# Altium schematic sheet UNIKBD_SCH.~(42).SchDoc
size A4
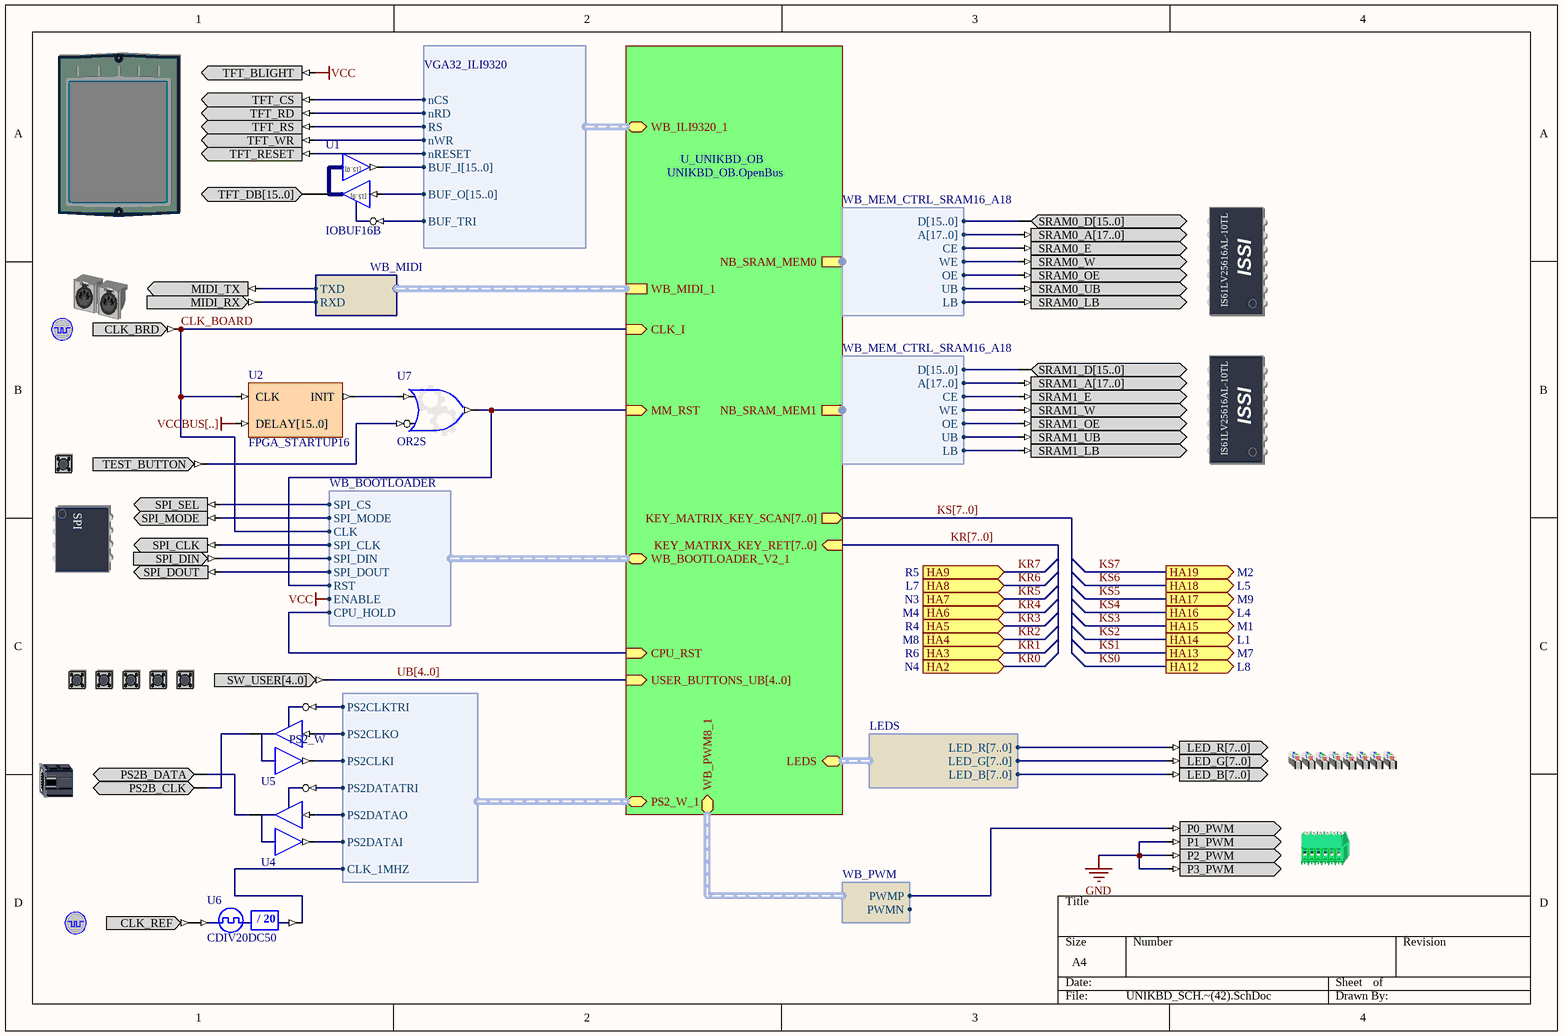
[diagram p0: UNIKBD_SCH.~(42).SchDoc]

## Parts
(Parts that share a designator on the sheet are numbered #1, #2 ... from top to bottom, then left to right.)
?#1  TFT_LCD  (value not drawn)
?#2  SRAM0  (value not drawn)
?#3  MIDI  (value not drawn)
?#4  CLOCK_BOARD  (value not drawn)
?#5  SRAM1  (value not drawn)
?#6  TEST_BUTTON  (value not drawn)
?#7  SERIALFMEMORY  (value not drawn)
?#8  USER_BUTTONS  (value not drawn)
?#9  LEDS_RGB  (value not drawn)
?#10  PS2B  (value not drawn)
?#11  PWM  (value not drawn)
?#12  CLOCK_REFERENCE  (value not drawn)
U1  IOBUF16B
U2  FPGA_STARTUP16
U4  IOBUF  (value not drawn)
U5  IOBUF  (value not drawn)
U6  CDIV20DC50
U7  OR2S

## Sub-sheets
U_UNIKBD_OB = UNIKBD_OB.OpenBus: KEY_MATRIX_KEY_SCAN[7..0] (out), KEY_MATRIX_KEY_RET[7..0] (in), WB_MIDI_1 (harness WB_MIDI), NB_SRAM_MEM0 (harness WB_MEM_CTRL_SRAM16_A18), NB_SRAM_MEM1 (harness WB_MEM_CTRL_SRAM16_A18), CLK_I (in), USER_BUTTONS_UB[4..0] (in), PS2_W_1 (harness PS2_W), LEDS (harness LEDS), WB_PWM8_1 (harness WB_PWM), WB_BOOTLOADER_V2_1 (harness WB_BOOTLOADER), MM_RST (in), CPU_RST (in), WB_ILI9320_1 (harness VGA32_ILI9320)

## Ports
HA2 (in, see N4), HA3 (in, see R6), HA4 (in, see M8), HA5 (in, see R4), HA6 (in, see M4), HA7 (in, see N3), HA8 (in, see L7), HA9 (in, see R5), HA12 (out, see L8), HA13 (out, see M7), HA14 (out, see L1), HA15 (out, see M1), HA16 (out, see L4), HA17 (out, see M9), HA18 (out, see L5), HA19 (out, see M2)

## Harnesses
WB_MEM_CTRL_SRAM16_A18: D[15..0], A[17..0], CE, WE, OE, UB, LB
WB_MIDI: RXD, TXD
LEDS: LED_R[7..0], LED_G[7..0], LED_B[7..0]
PS2_W: PS2CLKTRI, PS2CLKO, PS2CLKI, PS2DATATRI, PS2DATAO, PS2DATAI, CLK_1MHZ
WB_PWM: PWMN, PWMP
WB_BOOTLOADER: SPI_DOUT, SPI_DIN, SPI_CLK, SPI_MODE, SPI_CS, CLK, RST, ENABLE, CPU_HOLD
VGA32_ILI9320: BUF_TRI, BUF_O[15..0], BUF_I[15..0], nRESET, nWR, RS, nRD, nCS

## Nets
GND: ?#11.P1_PWM ?#11.P2_PWM ?#11.P3_PWM
VCC: ?#1.TFT_BLIGHT ; sheet U_UNIKBD_OB/WB_BOOTLOADER_V2_1.ENABLE
VCCBUS[..]: U2.DELAY[15..0]
CLK_BOARD: ?#4.CLK_BRD U2.CLK ; sheet U_UNIKBD_OB/CLK_I, sheet U_UNIKBD_OB/WB_BOOTLOADER_V2_1.CLK
Net?#1_TFT_CS: ?#1.TFT_CS ; sheet U_UNIKBD_OB/WB_ILI9320_1.nCS
Net?#1_TFT_DB[15..0]: ?#1.TFT_DB[15..0] U1.IO[15..0]
Net?#1_TFT_RD: ?#1.TFT_RD ; sheet U_UNIKBD_OB/WB_ILI9320_1.nRD
Net?#1_TFT_RESET: ?#1.TFT_RESET ; sheet U_UNIKBD_OB/WB_ILI9320_1.nRESET
Net?#1_TFT_RS: ?#1.TFT_RS ; sheet U_UNIKBD_OB/WB_ILI9320_1.RS
Net?#1_TFT_WR: ?#1.TFT_WR ; sheet U_UNIKBD_OB/WB_ILI9320_1.nWR
Net?#2_SRAM0_E: ?#2.SRAM0_E ; sheet U_UNIKBD_OB/NB_SRAM_MEM0.CE
Net?#2_SRAM0_LB: ?#2.SRAM0_LB ; sheet U_UNIKBD_OB/NB_SRAM_MEM0.LB
Net?#2_SRAM0_OE: ?#2.SRAM0_OE ; sheet U_UNIKBD_OB/NB_SRAM_MEM0.OE
Net?#2_SRAM0_UB: ?#2.SRAM0_UB ; sheet U_UNIKBD_OB/NB_SRAM_MEM0.UB
Net?#2_SRAM0_W: ?#2.SRAM0_W ; sheet U_UNIKBD_OB/NB_SRAM_MEM0.WE
Net?#3_MIDI_RX: ?#3.MIDI_RX ; sheet U_UNIKBD_OB/WB_MIDI_1.RXD
Net?#3_MIDI_TX: ?#3.MIDI_TX ; sheet U_UNIKBD_OB/WB_MIDI_1.TXD
Net?#5_SRAM1_E: ?#5.SRAM1_E ; sheet U_UNIKBD_OB/NB_SRAM_MEM1.CE
Net?#5_SRAM1_LB: ?#5.SRAM1_LB ; sheet U_UNIKBD_OB/NB_SRAM_MEM1.LB
Net?#5_SRAM1_OE: ?#5.SRAM1_OE ; sheet U_UNIKBD_OB/NB_SRAM_MEM1.OE
Net?#5_SRAM1_UB: ?#5.SRAM1_UB ; sheet U_UNIKBD_OB/NB_SRAM_MEM1.UB
Net?#5_SRAM1_W: ?#5.SRAM1_W ; sheet U_UNIKBD_OB/NB_SRAM_MEM1.WE
Net?#6_TEST_BUTTON: ?#6.TEST_BUTTON U7.I1
Net?#7_SPI_CLK: ?#7.SPI_CLK ; sheet U_UNIKBD_OB/WB_BOOTLOADER_V2_1.SPI_CLK
Net?#7_SPI_DIN: ?#7.SPI_DIN ; sheet U_UNIKBD_OB/WB_BOOTLOADER_V2_1.SPI_DIN
Net?#7_SPI_DOUT: ?#7.SPI_DOUT ; sheet U_UNIKBD_OB/WB_BOOTLOADER_V2_1.SPI_DOUT
Net?#7_SPI_MODE: ?#7.SPI_MODE ; sheet U_UNIKBD_OB/WB_BOOTLOADER_V2_1.SPI_MODE
Net?#7_SPI_SEL: ?#7.SPI_SEL ; sheet U_UNIKBD_OB/WB_BOOTLOADER_V2_1.SPI_CS
Net?#10_PS2B_CLK: ?#10.PS2B_CLK U5.IO
Net?#10_PS2B_DATA: ?#10.PS2B_DATA U4.IO
Net?#11_P0_PWM: ?#11.P0_PWM ; sheet U_UNIKBD_OB/WB_PWM8_1.PWMP
Net?#12_CLK_REF: ?#12.CLK_REF U6.CLKIN
NetU1_T: U1.T ; sheet U_UNIKBD_OB/WB_ILI9320_1.BUF_TRI
NetU2_INIT: U2.INIT U7.I0
NetU4_I: U4.I ; sheet U_UNIKBD_OB/PS2_W_1.PS2DATAO
NetU4_O: U4.O ; sheet U_UNIKBD_OB/PS2_W_1.PS2DATAI
NetU4_T: U4.T ; sheet U_UNIKBD_OB/PS2_W_1.PS2DATATRI
NetU5_I: U5.I ; sheet U_UNIKBD_OB/PS2_W_1.PS2CLKO
NetU5_O: U5.O ; sheet U_UNIKBD_OB/PS2_W_1.PS2CLKI
NetU5_T: U5.T ; sheet U_UNIKBD_OB/PS2_W_1.PS2CLKTRI
NetU6_CLKDV: U6.CLKDV ; sheet U_UNIKBD_OB/PS2_W_1.CLK_1MHZ
NetU7_O: U7.O ; sheet U_UNIKBD_OB/MM_RST, sheet U_UNIKBD_OB/WB_BOOTLOADER_V2_1.RST
(unnamed): sheet U_UNIKBD_OB/CPU_RST, sheet U_UNIKBD_OB/WB_BOOTLOADER_V2_1.CPU_HOLD

Not connected (* = marked no-connect by the designer): ?#2 SRAM0_A[17..0] SRAM0_D[15..0]; ?#5 SRAM1_A[17..0] SRAM1_D[15..0]; ?#8 SW_USER[4..0]; ?#9 LED_B[7..0] LED_G[7..0] LED_R[7..0]; U1 I[15..0] O[15..0]

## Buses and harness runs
bus KR[7..0] = sheet U_UNIKBD_OB/KEY_MATRIX_KEY_RET[7..0]
bus KS[7..0] = sheet U_UNIKBD_OB/KEY_MATRIX_KEY_SCAN[7..0]
bus UB[4..0] = sheet U_UNIKBD_OB/USER_BUTTONS_UB[4..0]

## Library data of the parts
?#1 = TFT_LCD: TFT LCD Panel; PortComponent: True
?#2 = SRAM0: Free Static RAM - Daughterboard; PortComponent: True
?#3 = MIDI: MIDI Connector; PortComponent: True
?#4 = CLOCK_BOARD: Global System Clock Supply; PortComponent: True
?#5 = SRAM1: Free Static RAM - Daughterboard; PortComponent: True
?#6 = TEST_BUTTON: Test / Reset Button; PortComponent: True
?#7 = SPI_BUS: Serial SPI Flash RAM; PortComponent: True
?#8 = USER_BUTTONS: Generic User Buttons; PortComponent: True
?#9 = LEDS_RGB: LEDS RGB; PortComponent: True
?#10 = PS2B: Key Board PS2 Connector; PortComponent: True
?#11 = PWM: Pulse Width Modulation; PortComponent: True
?#12 = CLOCK_REFERENCE: Global System Clock Reference Supply; PortComponent: True
U1 = IOBUF16B: 16-Bit Input/Output Buffer, Bus Version; SubClass: IOBUF; Enable: Low; Control: Common Control T; PortSize: 16; ArchiveName: GENERIC; VHDLIB_SIM: GENERIC_LIB
U2 = FPGA_STARTUP16: FPGA Startup With 16 Bit Delay
U4 U5 = IOBUF: Input/Output Buffer; Enable: Low; Control: Common Control T; ArchiveName: GENERIC; VHDLIB_SIM: GENERIC_LIB
U6 = CDIV20DC50: Clock Divider by 20 with 50% Duty Cycle Output; DivisorRate: 20; DutyCycle: 50; ArchiveName: GENERIC; VHDLIB_SIM: GENERIC_LIB
U7 = GATE: Configurable Generic Gate; ConfiguratorName: GENERIC_GATE; ConfigurationParameters: {}Version[1.0]{}GateKind[OR]{}BusInput[False]{}GateInputType[Bit]{}GateOutputOption[Normal]{}BusWidth[8]{}RegisterOutputs[False]{}NegativeClockEdge[False]{}InputCount[2]{}InputInvert0[False]{}InputInvert1[True]{}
